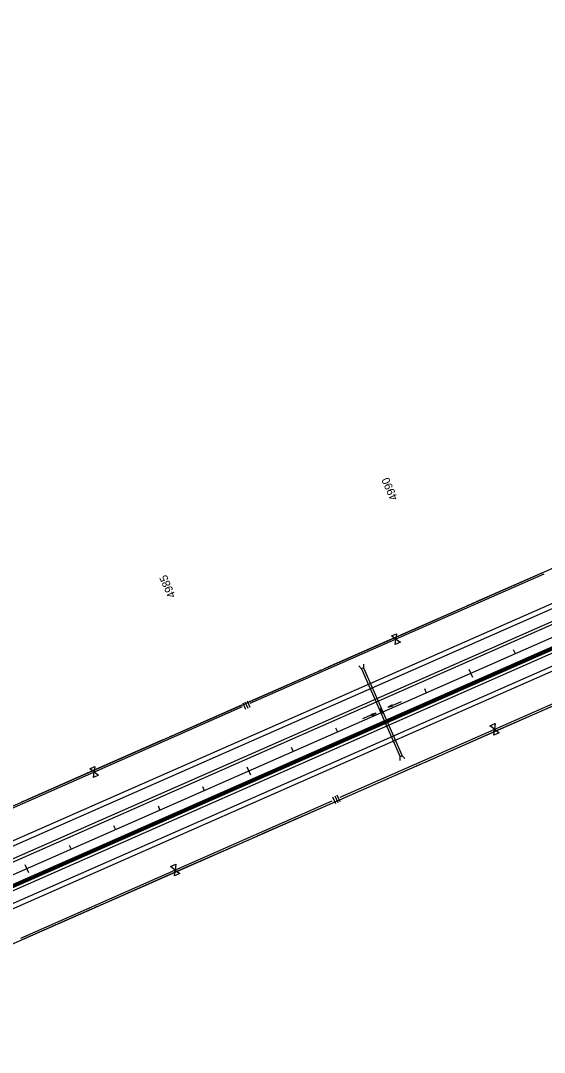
# Model space of a CAD drawing. Extents: x 192699 to 285914, y 194342 to 233219.
# Drawn here: x 243124 to 244204, y 221763 to 223889 of the extents above; entities that cross this region are included whole.
import ezdxf

# ---------------------------------------------------------------- set-up
doc = ezdxf.new("R2010")
doc.units = 0
for name, color, linetype in [('CENT LINE', 7, 'Continuous'), ('CONCRETE', 7, 'Continuous'), ('DRAINAGE', 7, 'Continuous'), ('DRAINAGE ARROWS', 7, 'Continuous'), ('R-W - CofA', 7, 'Continuous'), ('R_Water Annot', 7, 'Continuous'), ('ROAD', 7, 'Continuous'), ('SHOULDER', 7, 'Continuous'), ('STATIONING1', 7, 'Continuous'), ('WRSF', 7, 'Continuous')]:
    doc.layers.add(name, color=color, linetype=linetype)

msp = doc.modelspace()

# ---------------------------------------------------------------- linework, layer by layer
at = {"layer": 'CENT LINE'}
msp.add_line((229622.3, 216190.7), (246993.1, 223840), dxfattribs=at)
at = {"layer": 'CONCRETE'}
for p, q in [((237703.6, 219729.7), (244554.8, 222746.7)), ((237705.2, 219726), (244556.2, 222742.9))]:
    msp.add_line(p, q, dxfattribs=at)
at = {"layer": 'DRAINAGE'}
for p, q in [((243826.4, 222553.7), (243906.2, 222372.5)), ((243831, 222555.7), (243910.8, 222374.5))]:
    msp.add_line(p, q, dxfattribs=at)
for points in [[(243830.5, 222563.5), (243831, 222555.6)], [(243821.3, 222559.7), (243826.4, 222553.7)], [(243831, 222555.6), (243826.4, 222553.7)], [(243906.1, 222372.6), (243910.8, 222374.5)], [(243906.7, 222364.8), (243906.1, 222372.6)], [(243915.9, 222368.5), (243910.8, 222374.5)]]:
    msp.add_lwpolyline(points, dxfattribs=at)
msp.add_lwpolyline([(243867.5, 222461.5), (243871.2, 222463), (243869.7, 222466.7), (243866, 222465.2)], close=True, dxfattribs=at)
at = {"layer": 'DRAINAGE ARROWS'}
for p, q in [((243889.5, 222479), (243880.9, 222473.6)), ((243889.6, 222478.8), (243882.5, 222474.3)), ((243889.7, 222478.6), (243884, 222475)), ((243889.8, 222478.3), (243885.6, 222475.7)), ((243889.9, 222478.1), (243887.1, 222476.4)), ((243890, 222477.9), (243888.6, 222477)), ((243890.2, 222477.4), (243888.6, 222477)), ((243890.7, 222476.3), (243889.5, 222479)), ((243847.1, 222460.4), (243856.8, 222463.1)), ((243848.3, 222457.7), (243847.1, 222460.4)), ((243847.2, 222460.2), (243855.3, 222462.4)), ((243847.3, 222460), (243853.7, 222461.7)), ((243847.4, 222459.7), (243852.2, 222461)), ((243847.5, 222459.5), (243850.6, 222460.4)), ((243847.6, 222459.3), (243849.1, 222459.7)), ((243847.8, 222458.8), (243849.1, 222459.7)), ((243847.9, 222458.6), (243850.6, 222460.4)), ((243848, 222458.4), (243852.2, 222461)), ((243848.1, 222458.1), (243853.7, 222461.7)), ((243848.2, 222457.9), (243855.3, 222462.4)), ((243848.3, 222457.7), (243856.8, 222463.1)), ((243890.7, 222476.3), (243880.9, 222473.6)), ((243890.6, 222476.5), (243882.5, 222474.3)), ((243890.5, 222476.8), (243884, 222475)), ((243890.4, 222477), (243885.6, 222475.7)), ((243890.3, 222477.2), (243887.1, 222476.4))]:
    msp.add_line(p, q, dxfattribs=at)
at = {"layer": 'R-W - CofA'}
for p, q in [((243888.6, 222621.5), (243898.9, 222626)), ((243897.7, 222614.8), (243888.6, 222621.5)), ((243896.4, 222603.6), (243897.7, 222614.8)), ((243906.8, 222608.2), (243896.4, 222603.6)), ((243898.9, 222626), (243897.7, 222614.8)), ((243897.7, 222614.8), (243906.8, 222608.2)), ((243582, 222483.7), (243587.8, 222470.5)), ((243586.4, 222485.6), (243592.2, 222472.5)), ((243590.8, 222487.5), (243596.6, 222474.4)), ((244091.4, 222435.9), (244102.3, 222440.7)), ((244101, 222428.9), (244091.4, 222435.9)), ((244102.3, 222440.7), (244101, 222428.9)), ((244099.7, 222417), (244101, 222428.9)), ((244110.6, 222421.8), (244099.7, 222417)), ((244101, 222428.9), (244110.6, 222421.8)), ((243266.7, 222347.6), (243277, 222352.2)), ((243277, 222352.2), (243275.8, 222341)), ((243275.8, 222341), (243266.7, 222347.6)), ((243274.6, 222329.8), (243275.8, 222341)), ((243284.9, 222334.3), (243274.6, 222329.8)), ((243275.8, 222341), (243284.9, 222334.3)), ((243766.9, 222290), (243773, 222276.1)), ((243771.5, 222292.1), (243777.6, 222278.2)), ((243776.1, 222294.1), (243782.2, 222280.2)), ((243433, 222146), (243443.9, 222150.8)), ((243442.6, 222138.9), (243433, 222146)), ((243441.3, 222127.1), (243442.6, 222138.9)), ((243443.9, 222150.8), (243442.6, 222138.9)), ((243442.6, 222138.9), (243452.2, 222131.9)), ((243452.2, 222131.9), (243441.3, 222127.1))]:
    msp.add_line(p, q, dxfattribs=at)
for points in [[(240059.9, 220939.9), (241158.1, 221423.5), (241253.7, 221454.7), (244822.9, 223026.4), (245648.4, 223466.4)], [(239985.6, 220612.2), (240172.7, 220683.7), (241545.5, 221288.2), (241633, 221337.6), (244927.7, 222788.5), (245779.6, 223087.1), (245926, 223151.6)], [(243902.8, 222617.1), (244203.3, 222749.4)], [(244063.5, 222692), (244201.8, 222752.9)], [(244053.7, 222687.7), (244059.1, 222690.1)], [(243901.3, 222620.6), (244039.5, 222681.5)], [(244044, 222683.4), (244049.3, 222685.8)], [(243597.2, 222482.5), (243902.8, 222617.1)], [(243757.9, 222557.4), (243901.3, 222620.6)], [(244106.5, 222431.3), (244424.6, 222571.4)], [(243595.6, 222486), (243733.9, 222546.9)], [(243738.3, 222548.8), (243743.7, 222551.2)], [(243748.1, 222553.1), (243753.4, 222555.5)], [(243441.7, 222418.2), (243579.9, 222479.1)], [(244108.1, 222427.6), (244254.5, 222492)], [(243281, 222343.2), (243581.4, 222475.6)], [(243431.9, 222413.9), (243437.2, 222416.2)], [(243782.9, 222288.8), (244106.5, 222431.3)], [(243956.3, 222360.7), (244108.1, 222427.6)], [(243279.4, 222346.7), (243417.7, 222407.6)], [(243422.1, 222409.6), (243427.4, 222411.9)], [(243935.6, 222351.6), (243941.2, 222354.1)], [(243945.9, 222356.2), (243951.6, 222358.6)], [(242975.3, 222208.6), (243281, 222343.2)], [(243136, 222283.6), (243279.4, 222346.7)], [(243784.5, 222285.1), (243930.9, 222349.5)], [(243126.2, 222279.3), (243131.6, 222281.6)], [(243448.1, 222141.3), (243766.2, 222281.4)], [(243621.5, 222213.3), (243767.9, 222277.7)], [(243449.7, 222137.6), (243596.1, 222202.1)], [(243600.8, 222204.2), (243606.4, 222206.6)], [(243611.1, 222208.7), (243616.8, 222211.2)], [(243124.5, 221998.8), (243448.1, 222141.3)], [(243297.9, 222070.8), (243449.7, 222137.6)], [(243126.1, 221995.1), (243272.5, 222059.6)], [(243277.2, 222061.7), (243282.8, 222064.1)], [(243287.5, 222066.2), (243293.2, 222068.7)]]:
    msp.add_lwpolyline(points, dxfattribs=at)
at = {"layer": 'R_Water Annot'}
for p, q in [((243908.4, 222485.7), (243880.9, 222473.6)), ((243889.5, 222479), (243880.9, 222473.6)), ((243889.6, 222478.8), (243882.5, 222474.3)), ((243889.7, 222478.6), (243884, 222475)), ((243889.8, 222478.3), (243885.6, 222475.7)), ((243889.9, 222478.1), (243887.1, 222476.4)), ((243890, 222477.9), (243888.6, 222477)), ((243890.2, 222477.4), (243888.6, 222477)), ((243890.7, 222476.3), (243889.5, 222479)), ((243829.3, 222451.1), (243856.8, 222463.1)), ((243847.1, 222460.4), (243856.8, 222463.1)), ((243848.3, 222457.7), (243847.1, 222460.4)), ((243847.2, 222460.2), (243855.3, 222462.4)), ((243847.3, 222460), (243853.7, 222461.7)), ((243847.4, 222459.7), (243852.2, 222461)), ((243847.5, 222459.5), (243850.6, 222460.4)), ((243847.6, 222459.3), (243849.1, 222459.7)), ((243847.8, 222458.8), (243849.1, 222459.7)), ((243847.9, 222458.6), (243850.6, 222460.4)), ((243848, 222458.4), (243852.2, 222461)), ((243848.1, 222458.1), (243853.7, 222461.7)), ((243848.2, 222457.9), (243855.3, 222462.4)), ((243848.3, 222457.7), (243856.8, 222463.1)), ((243890.7, 222476.3), (243880.9, 222473.6)), ((243890.6, 222476.5), (243882.5, 222474.3)), ((243890.5, 222476.8), (243884, 222475)), ((243890.4, 222477), (243885.6, 222475.7)), ((243890.3, 222477.2), (243887.1, 222476.4))]:
    msp.add_line(p, q, dxfattribs=at)
at = {"layer": 'ROAD'}
for p, q in [((239472.3, 220587.2), (246971.3, 223889.4)), ((229610.2, 216218.1), (246981, 223867.5)), ((229634.4, 216163.2), (247005.2, 223812.6)), ((239989.5, 220696.9), (247014.8, 223790.6))]:
    msp.add_line(p, q, dxfattribs=at)
at = {"layer": 'SHOULDER'}
for p, q in [((239355.6, 220546.7), (244943.3, 223007.3)), ((237742, 219792.5), (244959.4, 222970.7)), ((237739.4, 219738.9), (244978.8, 222926.8)), ((239901.9, 220647.5), (244994.9, 222890.2))]:
    msp.add_line(p, q, dxfattribs=at)
at = {"layer": 'STATIONING1'}
for points in [[(244139.5, 222593.3), (244143.1, 222585)], [(244048, 222553), (244055.3, 222536.5)], [(243956.5, 222512.7), (243960.1, 222504.4)], [(243865, 222472.4), (243868.6, 222464.1)], [(243773.4, 222432.1), (243777.1, 222423.8)], [(243681.9, 222391.8), (243685.6, 222383.5)], [(243590.4, 222351.5), (243597.7, 222335)], [(243498.9, 222311.2), (243502.5, 222302.9)], [(243407.4, 222270.9), (243411, 222262.6)], [(243315.8, 222230.6), (243319.5, 222222.3)], [(243224.3, 222190.3), (243228, 222182)], [(243132.8, 222150), (243140.1, 222133.5)]]:
    msp.add_lwpolyline(points, dxfattribs=at)
at = {"layer": 'WRSF'}
msp.add_line((237704.4, 219727.8), (244555.5, 222744.8), dxfattribs=at)

# ---------------------------------------------------------------- texts
at = {"layer": 'STATIONING1'}
for s, p in [('4990', (243902.1, 222904.8)), ('4985', (243444.2, 222703.9))]:
    msp.add_text(s, height=16.5, rotation=113.7667, dxfattribs=at).set_placement(p)

doc.saveas('drawing.dxf')
